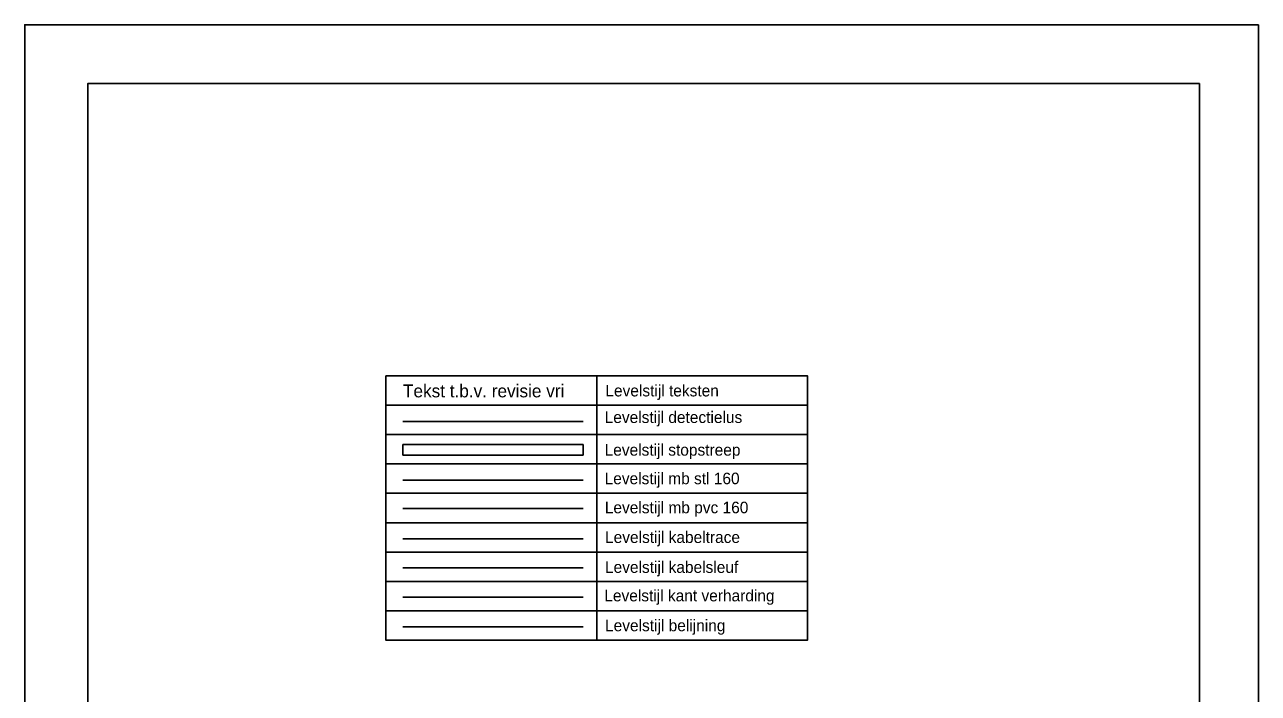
# Model space of a CAD drawing. Extents: x 133869.4 to 133911.4, y 396603.2 to 396662.6.
# Drawn here: x 133869.41 to 133911.41, y 396639.82 to 396662.58 of the extents above; entities that cross this region are included whole.
import ezdxf

# ---------------------------------------------------------------- set-up
doc = ezdxf.new("R2010")
doc.units = 0
for name, color, linetype in [('Ak-rand-kaderrand', 7, 'Continuous'), ('gg-knt-kant verharding', 7, 'Continuous'), ('IT-ANNO-LEGENDAS-VKRI', 7, 'Continuous'), ('IT-ANNO-TEXTEN-VKRI', 7, 'Continuous'), ('IT-BUIS-MANTELBUIS-160-PVC-VKRI', 7, 'Continuous'), ('IT-BUIS-MANTELBUIS-160-STAAL-VKRI', 7, 'Continuous'), ('IT-DET-DETECTIE-LUS IN ASFALT-VKRI', 7, 'Continuous'), ('IT-KABL-KABLSLEUF-VKRI', 7, 'Continuous'), ('IT-KABL-TRACE-VKRI', 7, 'Continuous'), ('IT-MARK-BELIJNINGEN-VKRI', 7, 'Continuous'), ('IT-MARK-STOPSTREPEN-VKRI', 7, 'Continuous')]:
    doc.layers.add(name, color=color, linetype=linetype)

msp = doc.modelspace()

# ---------------------------------------------------------------- linework, layer by layer
at = {"layer": 'Ak-rand-kaderrand'}
msp.add_lwpolyline([(133911.415, 396662.579), (133911.415, 396603.179), (133869.415, 396603.179), (133869.415, 396662.579)], close=True, dxfattribs=at)
msp.add_lwpolyline([(133909.415, 396660.579), (133871.57, 396660.579), (133871.57, 396605.179), (133909.415, 396605.179), (133909.415, 396660.579)], dxfattribs=at)
at = {"layer": 'gg-knt-kant verharding'}
msp.add_line((133882.294, 396643.088), (133888.424, 396643.088), dxfattribs=at)
at = {"layer": 'IT-ANNO-LEGENDAS-VKRI'}
for p, q in [((133881.713, 396649.628), (133888.889, 396649.628)), ((133888.889, 396649.628), (133896.065, 396649.628)), ((133881.713, 396648.628), (133888.889, 396648.628)), ((133888.889, 396648.628), (133896.065, 396648.628)), ((133881.713, 396647.628), (133888.889, 396647.628)), ((133888.889, 396647.628), (133896.065, 396647.628)), ((133881.713, 396646.628), (133888.889, 396646.628)), ((133888.889, 396646.628), (133896.065, 396646.628)), ((133881.713, 396645.628), (133888.889, 396645.628)), ((133888.889, 396645.628), (133896.065, 396645.628)), ((133881.713, 396644.628), (133888.889, 396644.628)), ((133888.889, 396644.628), (133896.065, 396644.628)), ((133881.713, 396643.628), (133888.889, 396643.628)), ((133888.889, 396643.628), (133896.065, 396643.628)), ((133881.713, 396642.628), (133888.889, 396642.628)), ((133888.889, 396642.628), (133896.065, 396642.628))]:
    msp.add_line(p, q, dxfattribs=at)
for points in [[(133881.713, 396650.628), (133888.889, 396650.628), (133888.889, 396641.628), (133881.713, 396641.628)], [(133888.889, 396650.628), (133896.065, 396650.628), (133896.065, 396641.628), (133888.889, 396641.628)]]:
    msp.add_lwpolyline(points, close=True, dxfattribs=at)
at = {"layer": 'IT-BUIS-MANTELBUIS-160-PVC-VKRI'}
msp.add_line((133882.294, 396646.109), (133888.424, 396646.109), dxfattribs=at)
at = {"layer": 'IT-BUIS-MANTELBUIS-160-STAAL-VKRI'}
msp.add_line((133882.294, 396647.074), (133888.424, 396647.074), dxfattribs=at)
at = {"layer": 'IT-DET-DETECTIE-LUS IN ASFALT-VKRI'}
msp.add_line((133882.294, 396649.075), (133888.424, 396649.075), dxfattribs=at)
at = {"layer": 'IT-KABL-KABLSLEUF-VKRI'}
msp.add_line((133882.294, 396644.089), (133888.424, 396644.089), dxfattribs=at)
at = {"layer": 'IT-KABL-TRACE-VKRI'}
msp.add_line((133882.294, 396645.074), (133888.424, 396645.074), dxfattribs=at)
at = {"layer": 'IT-MARK-BELIJNINGEN-VKRI'}
msp.add_line((133882.294, 396642.086), (133888.424, 396642.086), dxfattribs=at)
at = {"layer": 'IT-MARK-STOPSTREPEN-VKRI'}
for p, q in [((133882.294, 396648.291), (133888.424, 396648.291)), ((133882.294, 396647.926), (133882.294, 396648.291)), ((133888.424, 396648.291), (133888.424, 396647.926)), ((133888.424, 396647.926), (133882.294, 396647.926))]:
    msp.add_line(p, q, dxfattribs=at)

# ---------------------------------------------------------------- texts
at = {"layer": 'IT-ANNO-TEXTEN-VKRI'}
for s, height, p in [('Tekst t.b.v. revisie vri', 0.4375, (133882.294, 396649.894)), ('Levelstijl teksten', 0.39375, (133889.185, 396649.926)), ('Levelstijl detectielus', 0.39375, (133889.162, 396649.021)), ('Levelstijl stopstreep', 0.39375, (133889.16, 396647.909)), ('Levelstijl mb stl 160', 0.39375, (133889.16, 396646.937)), ('Levelstijl mb pvc 160', 0.39375, (133889.166, 396645.949)), ('Levelstijl kabeltrace', 0.39375, (133889.174, 396644.938)), ('Levelstijl kabelsleuf', 0.39375, (133889.172, 396643.919)), ('Levelstijl kant verharding', 0.39375, (133889.149, 396642.95)), ('Levelstijl belijning', 0.39375, (133889.174, 396641.933))]:
    msp.add_text(s, height=height, dxfattribs=at).set_placement(p)

doc.saveas('drawing.dxf')
